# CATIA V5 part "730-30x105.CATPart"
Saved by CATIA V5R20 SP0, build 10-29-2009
Part number: 730-30x105
Definition: NONE
Nomenclature: 730-30x105
Source: Unknown
Description: 730-30x105
Bounding box of the stored display mesh (mm): x -19 to 19, y -18.312 to 18.312, z 0 to 105
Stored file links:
  C:\Users\Utente\Desktop\IO LAVORO\3D X SITO CF\X SITO\730\730-30x105.CATPart
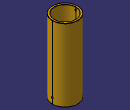
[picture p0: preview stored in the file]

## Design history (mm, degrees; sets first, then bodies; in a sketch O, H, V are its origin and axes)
Body1 "730-30x105" (main body)
  Solid1: solid without history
